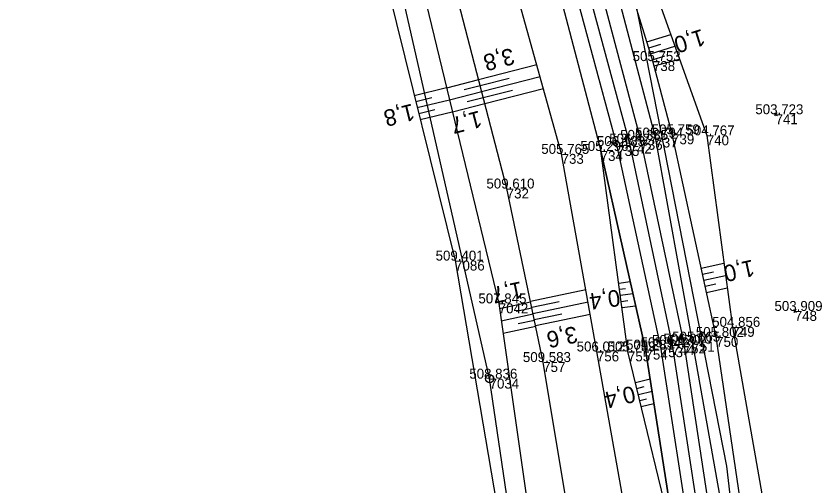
# Model space of a CAD drawing. Extents: x -1234191 to 23050, y -1290331 to -741191.
# Drawn here: x -865217.8 to -865120.5, y -1106168.8 to -1106112 of the extents above; entities that cross this region are included whole.
import ezdxf

# ---------------------------------------------------------------- set-up
doc = ezdxf.new("R2010")
doc.units = 0
for name, color, linetype in [('Vrstva 1', 7, 'Continuous'), ('Vrstva 4', 7, 'Continuous'), ('Vrstva 48', 7, 'Continuous'), ('Vrstva 49', 7, 'Continuous'), ('Vrstva 53', 7, 'Continuous'), ('Vrstva 60', 7, 'Continuous'), ('Vrstva 61', 7, 'Continuous')]:
    doc.layers.add(name, color=color, linetype=linetype)

msp = doc.modelspace()

# ---------------------------------------------------------------- linework, layer by layer
at = {"layer": 'Vrstva 1'}
msp.add_lwpolyline([(-865174.078, -1106040), (-865166.917, -1106056.414), (-865158.009, -1106079.457), (-865150.222, -1106103.276), (-865143.687, -1106127.439), (-865138.531, -1106151.753), (-865134.703, -1106176.737), (-865132.314, -1106201.517), (-865131.397, -1106219.01), (-865131.296, -1106235.963), (-865131.498, -1106253.761), (-865132.356, -1106271.324), (-865133.644, -1106288.752), (-865135.217, -1106305.905), (-865138.203, -1106334.815), (-865141.694, -1106364.628), (-865143.949, -1106381.706)], dxfattribs=at)
at = {"layer": 'Vrstva 4'}
for points in [[(-865236.512, -1105919.697), (-865214.371, -1105959.253), (-865205.708, -1105975.1), (-865197.042, -1105990.906), (-865188.447, -1106007.016), (-865180.581, -1106022.777), (-865172.438, -1106039.341), (-865165.467, -1106055.606), (-865156.604, -1106078.949), (-865148.774, -1106102.816), (-865142.368, -1106126.985), (-865137.15, -1106151.582), (-865133.366, -1106176.49), (-865130.909, -1106201.274), (-865129.854, -1106218.854), (-865129.682, -1106236.017), (-865129.855, -1106253.803), (-865130.861, -1106271.377), (-865132.166, -1106288.964), (-865133.635, -1106306.372), (-865136.705, -1106335.023), (-865140.22, -1106364.775), (-865141.258, -1106380.091)], [(-865141.696, -1106384.025), (-865141.482, -1106382.101), (-865141.258, -1106380.091), (-865140.926, -1106380.128), (-865137.571, -1106365.542), (-865134.22, -1106335.142), (-865132.239, -1106305.717), (-865130.429, -1106288.933), (-865129.368, -1106271.685), (-865128.102, -1106253.649), (-865128.268, -1106236.908), (-865128.835, -1106220.915), (-865128.917, -1106219.382), (-865128.786, -1106218.696), (-865129.184, -1106210.651), (-865129.217, -1106209.773), (-865129.126, -1106200.861), (-865131.77, -1106175.518), (-865136.087, -1106151.355), (-865140.565, -1106126.707), (-865146.909, -1106102.507), (-865155.58, -1106078.5), (-865164.275, -1106054.671), (-865171.298, -1106038.772)], [(-865177.512, -1106041.453), (-865169.991, -1106057.668), (-865161.369, -1106080.593), (-865153.442, -1106104.357), (-865147.172, -1106128.332), (-865141.755, -1106152.313), (-865137.812, -1106177.568), (-865135.396, -1106201.487), (-865134.525, -1106219.051), (-865134.216, -1106235.967), (-865134.596, -1106253.735), (-865135.575, -1106271.32), (-865136.694, -1106288.771), (-865137.937, -1106305.842), (-865141.065, -1106334.589), (-865145.11, -1106363.903), (-865146.295, -1106379.554), (-865145.893, -1106379.606)], [(-865145.893, -1106379.606), (-865143.239, -1106364.36), (-865139.628, -1106334.826), (-865136.464, -1106306.142), (-865135.094, -1106288.85), (-865133.928, -1106271.252), (-865133.164, -1106253.586), (-865132.64, -1106235.932), (-865133.104, -1106218.967), (-865133.768, -1106201.343), (-865136.102, -1106176.827), (-865139.914, -1106152.026), (-865145.177, -1106127.736), (-865151.699, -1106103.577), (-865159.145, -1106079.926), (-865168.183, -1106056.935), (-865175.375, -1106040.626)]]:
    msp.add_lwpolyline(points, dxfattribs=at)
at = {"layer": 'Vrstva 48'}
for p, q in [((-865141.583, -1106115.157), (-865138.71, -1106114.266)), ((-865141.361, -1106115.873), (-865139.909, -1106115.423)), ((-865141.139, -1106116.589), (-865138.204, -1106115.68)), ((-865140.917, -1106117.306), (-865139.434, -1106116.847)), ((-865140.719, -1106118.029), (-865137.652, -1106117.227)), ((-865161.925, -1106119.705), (-865154.892, -1106117.884)), ((-865161.549, -1106121.157), (-865154.49, -1106119.33)), ((-865161.919, -1106119.726), (-865165.783, -1106120.726)), ((-865161.737, -1106120.431), (-865158.214, -1106119.519)), ((-865169.677, -1106121.635), (-865165.795, -1106120.676)), ((-865161.543, -1106121.178), (-865165.43, -1106122.184)), ((-865161.731, -1106120.452), (-865163.669, -1106120.953)), ((-865161.361, -1106121.883), (-865157.825, -1106120.968)), ((-865161.173, -1106122.609), (-865154.088, -1106120.775)), ((-865169.498, -1106122.363), (-865167.558, -1106121.884)), ((-865169.318, -1106123.091), (-865165.442, -1106122.134)), ((-865161.355, -1106121.904), (-865163.304, -1106122.409)), ((-865161.167, -1106122.63), (-865165.076, -1106123.642)), ((-865169.138, -1106123.82), (-865167.201, -1106123.341)), ((-865168.958, -1106124.548), (-865165.089, -1106123.591)), ((-865135.04, -1106142.47), (-865132.29, -1106141.872)), ((-865134.881, -1106143.203), (-865133.536, -1106142.911)), ((-865134.722, -1106143.936), (-865132.09, -1106143.364)), ((-865145.002, -1106144.274), (-865143.614, -1106144.085)), ((-865134.562, -1106144.669), (-865133.276, -1106144.389)), ((-865155.659, -1106146.47), (-865148.964, -1106145.062)), ((-865144.901, -1106145.017), (-865144.175, -1106144.918)), ((-865144.8, -1106145.76), (-865143.282, -1106145.553)), ((-865134.403, -1106145.402), (-865131.89, -1106144.855)), ((-865155.634, -1106146.586), (-865159.391, -1106147.376)), ((-865155.504, -1106147.204), (-865152.168, -1106146.502)), ((-865155.35, -1106147.938), (-865148.7, -1106146.54)), ((-865144.699, -1106146.503), (-865143.907, -1106146.395)), ((-865155.48, -1106147.32), (-865157.382, -1106147.72)), ((-865144.598, -1106147.246), (-865142.95, -1106147.022)), ((-865155.325, -1106148.054), (-865159.179, -1106148.864)), ((-865155.196, -1106148.671), (-865151.882, -1106147.975)), ((-865155.041, -1106149.405), (-865148.436, -1106148.017)), ((-865155.017, -1106149.522), (-865158.967, -1106150.352)), ((-865155.171, -1106148.788), (-865157.122, -1106149.198)), ((-865155.041, -1106149.405), (-865155.041, -1106149.405)), ((-865142.974, -1106156.267), (-865141.205, -1106155.839)), ((-865142.797, -1106156.996), (-865141.943, -1106156.789)), ((-865142.62, -1106157.725), (-865140.972, -1106157.326)), ((-865142.444, -1106158.454), (-865141.65, -1106158.262)), ((-865142.267, -1106159.183), (-865140.74, -1106158.813))]:
    msp.add_line(p, q, dxfattribs=at)
at = {"layer": 'Vrstva 49'}
for p, q in [((-865126.258, -1106123.756), (-865125.838, -1106124.028)), ((-865125.912, -1106123.682), (-865126.184, -1106124.102)), ((-865123.945, -1106147.509), (-865123.525, -1106147.781)), ((-865123.599, -1106147.435), (-865123.871, -1106147.855))]:
    msp.add_line(p, q, dxfattribs=at)
for points in [[(-865248.477, -1105938.269), (-865237.75, -1105960.322), (-865218.997, -1105992.849), (-865195.388, -1106038.714), (-865183.023, -1106068.797), (-865169.187, -1106106.675), (-865159.482, -1106146.734), (-865152.519, -1106195.611), (-865150.401, -1106228.205), (-865149.999, -1106273.859), (-865151.773, -1106298.147), (-865154.534, -1106323.467), (-865155.1, -1106347.333), (-865155.484, -1106356.037)], [(-865145.942, -1106363.566), (-865142.639, -1106334.623), (-865139.289, -1106305.462), (-865137.62, -1106288.58), (-865139.326, -1106271.91), (-865139.98, -1106253.67), (-865139.709, -1106236.336), (-865140.161, -1106218.632), (-865140.504, -1106202.161), (-865143.149, -1106177.885), (-865147.628, -1106152.539), (-865151.892, -1106128.679), (-865158.014, -1106106.647), (-865166.095, -1106083.221), (-865174.808, -1106060.275), (-865182.221, -1106042.374), (-865189.981, -1106028.199), (-865197.424, -1106012.999), (-865203.011, -1106003.113), (-865213.201, -1105984.621), (-865220.397, -1105970.939), (-865239.793, -1105937.65)], [(-865155.484, -1106356.037), (-865151.68, -1106354.475), (-865149.301, -1106324.024), (-865147.432, -1106302.262), (-865147.231, -1106283.884), (-865146.7, -1106266.35), (-865146.428, -1106254.757), (-865146.524, -1106236.514), (-865147.193, -1106221.065), (-865147.912, -1106203.335), (-865150.128, -1106177.766), (-865154.114, -1106153.817), (-865158.519, -1106132.862), (-865164.631, -1106109.248), (-865174.131, -1106081.154), (-865182.296, -1106061.243), (-865188.604, -1106046.201), (-865195.382, -1106031.759), (-865203.752, -1106015.412), (-865210.877, -1106001.893), (-865218.69, -1105987.336), (-865233.439, -1105960.203), (-865244.504, -1105938.746)], [(-865127.373, -1106218.557), (-865126.999, -1106201.036), (-865129.615, -1106175.312), (-865133.233, -1106150.782), (-865138.553, -1106126.314), (-865140.864, -1106117.476), (-865147.92, -1106094.705), (-865153.785, -1106077.739), (-865163.009, -1106054.441), (-865168.926, -1106038.436), (-865178.612, -1106020.847), (-865186.958, -1106006.274), (-865196.357, -1105989.486), (-865203.414, -1105973.739), (-865210.89, -1105957.767), (-865215.998, -1105940.862)], [(-865215.998, -1105940.862), (-865209.598, -1105955.153), (-865202.33, -1105969.043), (-865194.328, -1105988.74), (-865185.257, -1106005.628), (-865177.356, -1106020.263), (-865168.926, -1106038.436), (-865158.936, -1106054.901), (-865150.766, -1106078.052), (-865143.254, -1106101.545), (-865134.359, -1106126.445), (-865131.259, -1106149.565), (-865127.173, -1106172.699), (-865123.902, -1106198.296), (-865127.373, -1106218.557)], [(-865172.838, -1106108.847), (-865164.752, -1106141.565), (-865157.427, -1106184.617), (-865155.731, -1106196.419), (-865153.255, -1106230.421), (-865153.124, -1106269.971), (-865155.126, -1106299.71), (-865157.116, -1106321.563), (-865157.695, -1106345.273), (-865155.484, -1106356.037)], [(-865137.812, -1106177.568), (-865143.878, -1106152.535), (-865147.172, -1106128.332)], [(-865137.62, -1106288.58), (-865135.575, -1106271.32), (-865134.596, -1106253.735), (-865134.216, -1106235.967), (-865134.525, -1106219.051), (-865135.396, -1106201.487), (-865137.812, -1106177.568), (-865141.755, -1106152.313), (-865147.172, -1106128.332)]]:
    msp.add_lwpolyline(points, dxfattribs=at)
at = {"layer": 'Vrstva 53'}
msp.add_line((-865160.594, -1106155.773), (-865160.578, -1106155.871), dxfattribs=at)
for points in [[(-865227.657, -1105917.883), (-865232.359, -1105922.352), (-865183.089, -1106010.413), (-865167.993, -1106045.384), (-865144.776, -1106101.17), (-865131.987, -1106166.385), (-865125.846, -1106219.007), (-865125.39, -1106238.65), (-865125.959, -1106278.896), (-865132.866, -1106334.647), (-865136.846, -1106381.378), (-865151.633, -1106445.098), (-865163.441, -1106490.832), (-865178.818, -1106535.037), (-865200.93, -1106584.091), (-865238.815, -1106657.436), (-865256.949, -1106698.525)], [(-865292.282, -1106759.439), (-865281.001, -1106690.918), (-865292.094, -1106688.295), (-865256.125, -1106617.237), (-865192.39, -1106497.22), (-865182.07, -1106466.18), (-865172.595, -1106441.084), (-865160.974, -1106443.618), (-865159.329, -1106435.017), (-865146.435, -1106359.55), (-865157.508, -1106356.946), (-865157.004, -1106331.907), (-865151.899, -1106265.922), (-865152.14, -1106213.17), (-865160.59, -1106155.82), (-865173.125, -1106100.651), (-865192.842, -1106055.27), (-865212.4, -1106009.433), (-865251.569, -1105941.084), (-865241.975, -1105927.132)]]:
    msp.add_lwpolyline(points, dxfattribs=at)
msp.add_circle((-865160.586, -1106155.822), 0.499, dxfattribs=at)
at = {"layer": 'Vrstva 60'}
for p, q in [((-865140.864, -1106117.476), (-865140.864, -1106117.476)), ((-865126.048, -1106123.892), (-865126.048, -1106123.892)), ((-865142.368, -1106126.985), (-865142.368, -1106126.985)), ((-865140.565, -1106126.707), (-865140.565, -1106126.707)), ((-865138.553, -1106126.314), (-865138.553, -1106126.314)), ((-865134.359, -1106126.445), (-865134.359, -1106126.445)), ((-865145.177, -1106127.736), (-865145.177, -1106127.736)), ((-865143.687, -1106127.439), (-865143.687, -1106127.439)), ((-865151.892, -1106128.679), (-865151.892, -1106128.679)), ((-865147.172, -1106128.332), (-865147.172, -1106128.332)), ((-865158.519, -1106132.862), (-865158.519, -1106132.862)), ((-865164.752, -1106141.565), (-865164.752, -1106141.565)), ((-865159.482, -1106146.734), (-865159.482, -1106146.734)), ((-865123.735, -1106147.645), (-865123.735, -1106147.645)), ((-865131.259, -1106149.565), (-865131.259, -1106149.565)), ((-865136.087, -1106151.355), (-865136.087, -1106151.355)), ((-865133.233, -1106150.782), (-865133.233, -1106150.782)), ((-865141.755, -1106152.313), (-865141.755, -1106152.313)), ((-865139.914, -1106152.026), (-865139.914, -1106152.026)), ((-865138.531, -1106151.753), (-865138.531, -1106151.753)), ((-865137.15, -1106151.582), (-865137.15, -1106151.582)), ((-865147.628, -1106152.539), (-865147.628, -1106152.539)), ((-865143.878, -1106152.535), (-865143.878, -1106152.535)), ((-865154.114, -1106153.817), (-865154.114, -1106153.817)), ((-865160.586, -1106155.822), (-865160.586, -1106155.822))]:
    msp.add_line(p, q, dxfattribs=at)

# ---------------------------------------------------------------- texts
at = {"layer": 'Vrstva 48'}
for s, rotation, p in [('1,0', 197.21653, (-865134.948, -1106113.563)), ('3,8', 194.51138, (-865157.898, -1106115.857)), ('1,8', 193.88203, (-865169.926, -1106122.592)), ('1,7', 194.51138, (-865161.826, -1106123.431)), ('1,0', 192.26672, (-865128.849, -1106141.431)), ('1,7', 191.87143, (-865156.815, -1106144.057)), ('0,4', 187.75027, (-865144.974, -1106145.044)), ('3,6', 191.87143, (-865150.203, -1106149.448)), ('0,4', 193.62136, (-865143.27, -1106156.644))]:
    msp.add_text(s, height=2, rotation=rotation, dxfattribs=at).set_placement(p)
at = {"layer": 'Vrstva 60'}
for s, p in [('738', (-865140.864, -1106118.676)), ('741', (-865126.048, -1106125.092)), ('736', (-865142.368, -1106128.185)), ('737', (-865140.565, -1106127.907)), ('739', (-865138.553, -1106127.514)), ('740', (-865134.359, -1106127.645)), ('735', (-865145.177, -1106128.936)), ('742', (-865143.687, -1106128.639)), ('733', (-865151.892, -1106129.879)), ('734', (-865147.172, -1106129.532)), ('732', (-865158.519, -1106134.062)), ('7086', (-865164.752, -1106142.765)), ('7042', (-865159.482, -1106147.934)), ('748', (-865123.735, -1106148.845)), ('749', (-865131.259, -1106150.765)), ('751', (-865136.087, -1106152.555)), ('750', (-865133.233, -1106151.982)), ('754', (-865141.755, -1106153.513)), ('753', (-865139.914, -1106153.226)), ('744', (-865138.531, -1106152.953)), ('752', (-865137.15, -1106152.782)), ('756', (-865147.628, -1106153.739)), ('755', (-865143.878, -1106153.735)), ('757', (-865154.114, -1106155.017)), ('7034', (-865160.586, -1106157.022))]:
    msp.add_text(s, height=1.2, dxfattribs=at).set_placement(p)
at = {"layer": 'Vrstva 61'}
for s, p in [('505.753', (-865143.316, -1106117.476)), ('503.723', (-865128.5, -1106123.892)), ('505.759', (-865141.007, -1106126.314)), ('506.335', (-865144.824, -1106126.985)), ('505.794', (-865143.016, -1106126.707)), ('504.767', (-865136.811, -1106126.445)), ('505.296', (-865149.624, -1106128.332)), ('506.183', (-865147.629, -1106127.736)), ('506.427', (-865146.139, -1106127.439)), ('505.765', (-865154.348, -1106128.679)), ('509.610', (-865160.97, -1106132.862)), ('509.401', (-865167.109, -1106141.565)), ('507.845', (-865161.938, -1106146.734)), ('503.909', (-865126.189, -1106147.645)), ('504.856', (-865133.711, -1106149.565)), ('506.070', (-865139.601, -1106151.582)), ('505.665', (-865138.543, -1106151.355)), ('505.802', (-865135.681, -1106150.782)), ('506.012', (-865150.076, -1106152.539)), ('505.759', (-865146.332, -1106152.535)), ('505.231', (-865144.112, -1106152.313)), ('505.942', (-865142.362, -1106152.026)), ('506.170', (-865140.982, -1106151.753)), ('509.583', (-865156.566, -1106153.817)), ('508.836', (-865163.038, -1106155.822))]:
    msp.add_text(s, height=1.2, dxfattribs=at).set_placement(p)

doc.saveas('drawing.dxf')
